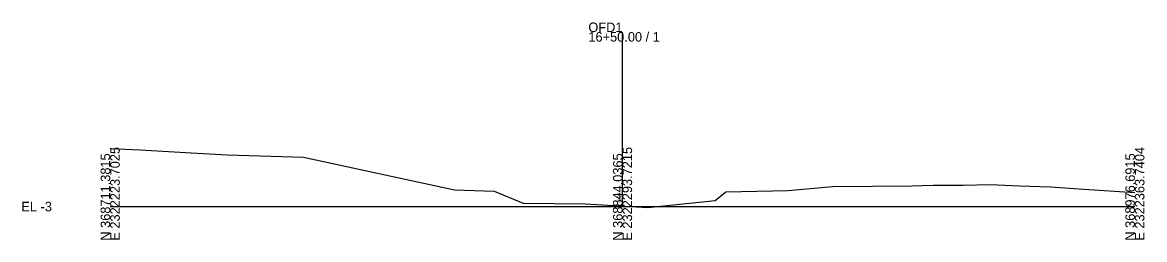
# Model space of a CAD drawing. Extents: x -26 to 303, y -10 to 14048.
# Drawn here: x -25.7 to 302.8, y 12990.3 to 13054 of the extents above; entities that cross this region are included whole.
import ezdxf

# ---------------------------------------------------------------- set-up
doc = ezdxf.new("R2010")
doc.units = 0
for name, color, linetype in [('RD_GPK_XS_Cell', 7, 'Continuous'), ('RD_XS_ExGround', 7, 'Continuous'), ('RD_XS_TX_Elev_EX', 7, 'Continuous')]:
    doc.layers.add(name, color=color, linetype=linetype)

msp = doc.modelspace()

# ---------------------------------------------------------------- linework, layer by layer
at = {"layer": 'RD_GPK_XS_Cell'}
for p, q in [((150, 13000), (150, 13051.19)), ((0, 13000), (150, 13000)), ((150, 13000), (300, 13000))]:
    msp.add_line(p, q, dxfattribs=at)
at = {"layer": 'RD_XS_ExGround'}
for p, q in [((0, 13017.06), (8.75, 13016.6)), ((8.75, 13016.6), (23.68, 13015.74)), ((23.68, 13015.74), (34.35, 13015.15)), ((34.35, 13015.15), (56.55, 13014.49)), ((56.55, 13014.49), (100.81, 13004.91)), ((100.81, 13004.91), (112.41, 13004.51)), ((112.41, 13004.51), (120.93, 13001.04)), ((177.11, 13001.75), (180.2, 13004.36)), ((180.2, 13004.36), (198.5, 13004.72)), ((198.5, 13004.72), (211.43, 13005.84)), ((211.43, 13005.84), (223.23, 13006.02)), ((223.23, 13006.02), (234.75, 13006.04)), ((234.75, 13006.04), (240.95, 13006.23)), ((240.95, 13006.23), (249.71, 13006.32)), ((249.71, 13006.32), (257.61, 13006.45)), ((257.61, 13006.45), (266.23, 13006.06)), ((266.23, 13006.06), (275.27, 13005.76)), ((275.27, 13005.76), (282.25, 13005.34)), ((282.25, 13005.34), (285.02, 13005.07)), ((285.02, 13005.07), (300, 13004.11)), ((120.93, 13001.04), (139.09, 13000.83)), ((139.09, 13000.83), (157.4, 12999.76)), ((157.4, 12999.76), (177.11, 13001.75))]:
    msp.add_line(p, q, dxfattribs=at)

# ---------------------------------------------------------------- texts
at = {"layer": 'RD_GPK_XS_Cell'}
for s, p in [('OFD1', (140, 13051.19)), ('16+50.00 / 1', (140, 13048.39)), ('EL -3', (-26, 12998.6))]:
    msp.add_text(s, height=2.8, dxfattribs=at).set_placement(p)
for s, p in [('E 2322223.7025', (2.8, 12990)), ('E 2322293.7215', (152.8, 12990)), ('E 2322363.7404', (302.8, 12990)), ('N 368711.3815', (0, 12990)), ('N 368844.0365', (150, 12990)), ('N 368976.6915', (300, 12990))]:
    msp.add_text(s, height=2.8, rotation=90, dxfattribs=at).set_placement(p)
at = {"layer": 'RD_XS_TX_Elev_EX'}
msp.add_text('-3.07', height=1, rotation=90, dxfattribs=at).set_placement((149.5, 13000.93))

doc.saveas('drawing.dxf')
